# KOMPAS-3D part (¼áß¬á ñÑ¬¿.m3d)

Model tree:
1. Эскиз:1
2. Операция выдавливания:24
     Толщина стенки 2 = 10; Расстояние 1 = 0.6
3. Эскиз:22
4. Операция выдавливания:25
     Толщина стенки 1 = 6; Толщина стенки 2 = 6; Расстояние 1 = 0.6
5. Эскиз:23
6. Операция выдавливания:26
     Толщина стенки 1 = 6; Толщина стенки 2 = 6; Расстояние 1 = 0.6
7. Эскиз:24
8. Операция выдавливания:27
     Толщина стенки 1 = 6; Толщина стенки 2 = 6; Расстояние 1 = 0.6
